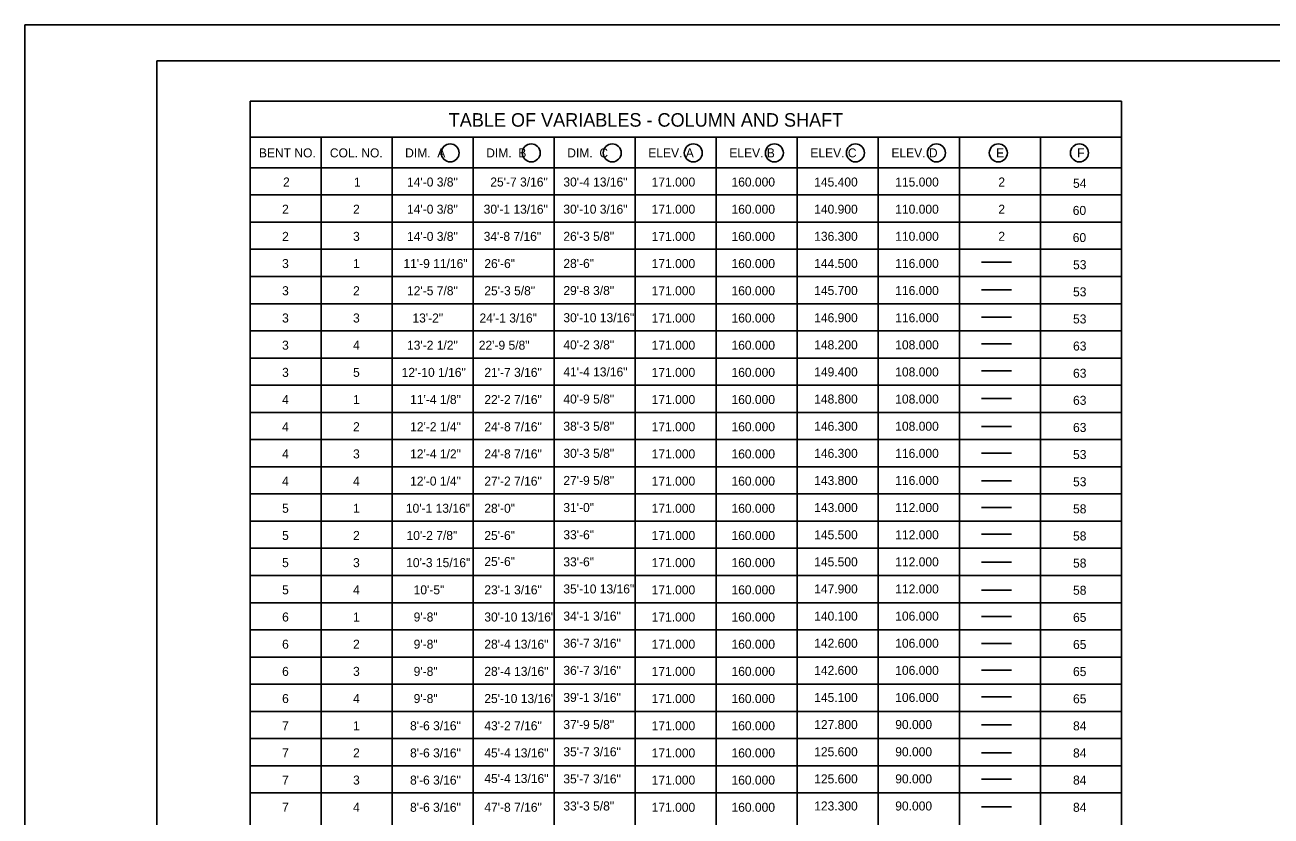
# Model space of a CAD drawing. Extents: x -133.1 to -97, y -1.7 to 20.3.
# Drawn here: x -133.14 to -115.84, y 9.34 to 20.31 of the extents above; entities that cross this region are included whole.
import ezdxf

# ---------------------------------------------------------------- set-up
doc = ezdxf.new("R2010")
doc.units = 0
for name, color, linetype in [('BR_AUTO DIMENSION', 7, 'Continuous'), ('BR_BORDER LINES', 7, 'Continuous'), ('BR_TABLE LINES', 7, 'Continuous'), ('BR_TEXT', 7, 'Continuous'), ('Level 31', 7, 'Continuous')]:
    doc.layers.add(name, color=color, linetype=linetype)

msp = doc.modelspace()

# ---------------------------------------------------------------- linework, layer by layer
at = {"layer": 'BR_AUTO DIMENSION'}
for p, q in [((-120.17, -0.146), (-120.17, 18.753)), ((-119.045, -0.146), (-119.045, 18.753))]:
    msp.add_line(p, q, dxfattribs=at)
at = {"layer": 'BR_BORDER LINES'}
for p in [(-97.642, 19.809), (-131.308, -1.191)]:
    msp.add_line(p, (-131.308, 19.809), dxfattribs=at)
at = {"layer": 'BR_TABLE LINES'}
for p, q in [((-130.014, 19.253), (-117.92, 19.253)), ((-130.014, -0.146), (-130.014, 19.253)), ((-117.92, -0.146), (-117.92, 19.253)), ((-130.014, 18.753), (-117.92, 18.753)), ((-129.03, -0.146), (-129.029, 18.753)), ((-128.045, -0.146), (-128.045, 18.753)), ((-126.92, -0.146), (-126.92, 18.753)), ((-125.795, -0.146), (-125.795, 18.753)), ((-124.67, -0.146), (-124.67, 18.753)), ((-123.545, -0.146), (-123.545, 18.753)), ((-122.42, -0.146), (-122.42, 18.753)), ((-121.295, -0.146), (-121.295, 18.753)), ((-120.17, -0.146), (-120.17, 18.753)), ((-119.045, -0.146), (-119.045, 18.753)), ((-130.014, 18.329), (-117.92, 18.329)), ((-130.014, 17.951), (-117.92, 17.951)), ((-130.014, 17.574), (-117.92, 17.574)), ((-130.014, 17.197), (-117.92, 17.197)), ((-130.014, 16.82), (-117.92, 16.82)), ((-130.014, 16.443), (-117.92, 16.443)), ((-130.014, 16.066), (-117.92, 16.066)), ((-130.014, 15.689), (-117.92, 15.689)), ((-130.014, 15.312), (-117.92, 15.312)), ((-130.014, 14.935), (-117.92, 14.935)), ((-130.014, 14.558), (-117.92, 14.558)), ((-130.014, 14.181), (-117.92, 14.181)), ((-130.014, 13.804), (-117.92, 13.804)), ((-130.014, 13.427), (-117.92, 13.427)), ((-130.014, 13.05), (-117.92, 13.05)), ((-130.014, 12.673), (-117.92, 12.673)), ((-130.014, 12.296), (-117.92, 12.296)), ((-130.014, 11.919), (-117.92, 11.919)), ((-130.014, 11.542), (-117.92, 11.542)), ((-130.014, 11.165), (-117.92, 11.165)), ((-130.014, 10.788), (-117.92, 10.788)), ((-130.014, 10.411), (-117.92, 10.411)), ((-130.014, 10.034), (-117.92, 10.034)), ((-130.014, 9.657), (-117.92, 9.657))]:
    msp.add_line(p, q, dxfattribs=at)
at = {"layer": 'BR_TEXT'}
for p, q in [((-119.863, 17.02), (-119.445, 17.02)), ((-119.863, 16.633), (-119.445, 16.633)), ((-119.863, 16.254), (-119.445, 16.254)), ((-119.863, 15.884), (-119.445, 15.884)), ((-119.863, 15.514), (-119.445, 15.514)), ((-119.863, 15.126), (-119.445, 15.126)), ((-119.863, 14.738), (-119.445, 14.738)), ((-119.863, 14.37), (-119.445, 14.37)), ((-119.863, 13.986), (-119.445, 13.986)), ((-119.863, 13.616), (-119.445, 13.616)), ((-119.863, 13.246), (-119.445, 13.246)), ((-119.863, 12.858), (-119.445, 12.858)), ((-119.863, 12.47), (-119.445, 12.47)), ((-119.863, 12.103), (-119.445, 12.103)), ((-119.863, 11.731), (-119.445, 11.731)), ((-119.863, 11.361), (-119.445, 11.361)), ((-119.863, 10.991), (-119.445, 10.991)), ((-119.863, 10.603), (-119.445, 10.603)), ((-119.863, 10.215), (-119.445, 10.215)), ((-119.863, 9.847), (-119.445, 9.847)), ((-119.863, 9.467), (-119.445, 9.467))]:
    msp.add_line(p, q, dxfattribs=at)
for centre in [(-127.238, 18.535), (-126.113, 18.535), (-124.988, 18.535), (-123.863, 18.535), (-122.738, 18.535), (-121.613, 18.535), (-120.488, 18.535), (-119.629, 18.535), (-119.629, 18.535), (-118.504, 18.535)]:
    msp.add_circle(centre, 0.125, dxfattribs=at)
at = {"layer": 'Level 31'}
msp.add_lwpolyline([(-133.141, -1.691), (-97.141, -1.691), (-97.141, 20.309), (-133.141, 20.309)], close=True, dxfattribs=at)

# ---------------------------------------------------------------- texts
at = {"layer": 'BR_TEXT'}
msp.add_text('TABLE OF VARIABLES - COLUMN AND SHAFT', height=0.1875, dxfattribs=at).set_placement((-127.258, 18.898))
for s, p in [('BENT NO.', (-129.893, 18.472)), ('COL. NO.', (-128.908, 18.472)), ('DIM.  A', (-127.863, 18.472)), ('DIM.  B', (-126.738, 18.472)), ('DIM.  C', (-125.613, 18.472)), ('ELEV. A', (-124.488, 18.472)), ('ELEV. B', (-123.363, 18.472)), ('ELEV. C', (-122.238, 18.472)), ('ELEV. D', (-121.113, 18.472)), ('F', (-119.66, 18.472)), ('E', (-119.66, 18.472)), ('F', (-118.535, 18.472)), ('2', (-129.558, 18.068)), ('1', (-128.573, 18.068)), ('14\'-0 3/8"', (-127.837, 18.068)), ('25\'-7 3/16"', (-126.681, 18.068)), ('30\'-4 13/16"', (-125.667, 18.068)), ('171.000', (-124.441, 18.068)), ('160.000', (-123.333, 18.068)), ('145.400', (-122.185, 18.068)), ('115.000', (-121.06, 18.068)), ('2', (-119.629, 18.068)), ('54', (-118.592, 18.05)), ('2', (-129.571, 17.691)), ('2', (-128.586, 17.691)), ('14\'-0 3/8"', (-127.837, 17.691)), ('30\'-1 13/16"', (-126.773, 17.691)), ('30\'-10 3/16"', (-125.667, 17.691)), ('171.000', (-124.441, 17.691)), ('160.000', (-123.333, 17.691)), ('140.900', (-122.185, 17.691)), ('110.000', (-121.06, 17.691)), ('2', (-119.629, 17.691)), ('60', (-118.596, 17.674)), ('2', (-129.571, 17.314)), ('3', (-128.586, 17.314)), ('14\'-0 3/8"', (-127.837, 17.314)), ('34\'-8 7/16"', (-126.773, 17.314)), ('26\'-3 5/8"', (-125.667, 17.315)), ('171.000', (-124.441, 17.314)), ('160.000', (-123.333, 17.314)), ('136.300', (-122.185, 17.315)), ('110.000', (-121.06, 17.315)), ('2', (-119.629, 17.315)), ('60', (-118.596, 17.298)), ('3', (-129.571, 16.937)), ('1', (-128.586, 16.937)), ('11\'-9 11/16"', (-127.887, 16.937)), ('26\'-6"', (-126.764, 16.937)), ('28\'-6"', (-125.667, 16.939)), ('171.000', (-124.441, 16.937)), ('160.000', (-123.333, 16.937)), ('144.500', (-122.185, 16.939)), ('116.000', (-121.06, 16.939)), ('53', (-118.592, 16.921)), ('3', (-129.571, 16.56)), ('2', (-128.586, 16.56)), ('12\'-5 7/8"', (-127.837, 16.56)), ('25\'-3 5/8"', (-126.764, 16.56)), ('29\'-8 3/8"', (-125.667, 16.563)), ('171.000', (-124.441, 16.56)), ('160.000', (-123.333, 16.56)), ('145.700', (-122.185, 16.563)), ('116.000', (-121.06, 16.563)), ('53', (-118.592, 16.545)), ('3', (-129.571, 16.182)), ('3', (-128.586, 16.182)), ('13\'-2"', (-127.762, 16.182)), ('24\'-1 3/16"', (-126.831, 16.182)), ('30\'-10 13/16"', (-125.667, 16.186)), ('171.000', (-124.441, 16.182)), ('160.000', (-123.333, 16.182)), ('146.900', (-122.185, 16.186)), ('116.000', (-121.06, 16.186)), ('53', (-118.592, 16.169)), ('3', (-129.571, 15.805)), ('4', (-128.586, 15.805)), ('13\'-2 1/2"', (-127.837, 15.805)), ('22\'-9 5/8"', (-126.841, 15.805)), ('40\'-2 3/8"', (-125.667, 15.81)), ('171.000', (-124.441, 15.805)), ('160.000', (-123.333, 15.805)), ('148.200', (-122.185, 15.81)), ('108.000', (-121.06, 15.81)), ('63', (-118.592, 15.793)), ('3', (-129.571, 15.428)), ('5', (-128.586, 15.428)), ('12\'-10 1/16"', (-127.912, 15.428)), ('21\'-7 3/16"', (-126.764, 15.428)), ('41\'-4 13/16"', (-125.667, 15.434)), ('171.000', (-124.441, 15.428)), ('160.000', (-123.333, 15.428)), ('149.400', (-122.185, 15.434)), ('108.000', (-121.06, 15.434)), ('63', (-118.592, 15.416)), ('4', (-129.571, 15.051)), ('1', (-128.586, 15.051)), ('11\'-4 1/8"', (-127.794, 15.051)), ('22\'-2 7/16"', (-126.764, 15.051)), ('40\'-9 5/8"', (-125.667, 15.058)), ('171.000', (-124.441, 15.051)), ('160.000', (-123.333, 15.051)), ('148.800', (-122.185, 15.058)), ('108.000', (-121.06, 15.058)), ('63', (-118.592, 15.04)), ('4', (-129.571, 14.674)), ('2', (-128.586, 14.674)), ('12\'-2 1/4"', (-127.794, 14.674)), ('24\'-8 7/16"', (-126.764, 14.674)), ('38\'-3 5/8"', (-125.667, 14.681)), ('171.000', (-124.441, 14.674)), ('160.000', (-123.333, 14.674)), ('146.300', (-122.185, 14.681)), ('108.000', (-121.06, 14.681)), ('63', (-118.592, 14.664)), ('4', (-129.571, 14.297)), ('3', (-128.586, 14.297)), ('12\'-4 1/2"', (-127.794, 14.297)), ('24\'-8 7/16"', (-126.764, 14.297)), ('30\'-3 5/8"', (-125.667, 14.305)), ('171.000', (-124.441, 14.297)), ('160.000', (-123.333, 14.297)), ('146.300', (-122.185, 14.305)), ('116.000', (-121.06, 14.305)), ('53', (-118.592, 14.288)), ('4', (-129.571, 13.92)), ('4', (-128.586, 13.92)), ('12\'-0 1/4"', (-127.794, 13.92)), ('27\'-2 7/16"', (-126.764, 13.92)), ('27\'-9 5/8"', (-125.667, 13.929)), ('171.000', (-124.441, 13.92)), ('160.000', (-123.333, 13.92)), ('143.800', (-122.185, 13.929)), ('116.000', (-121.06, 13.929)), ('53', (-118.592, 13.911)), ('5', (-129.571, 13.543)), ('1', (-128.586, 13.543)), ('10\'-1 13/16"', (-127.853, 13.543)), ('28\'-0"', (-126.764, 13.543)), ('31\'-0"', (-125.667, 13.553)), ('171.000', (-124.441, 13.543)), ('160.000', (-123.333, 13.543)), ('143.000', (-122.185, 13.553)), ('112.000', (-121.06, 13.553)), ('58', (-118.592, 13.535)), ('5', (-129.571, 13.166)), ('2', (-128.586, 13.166)), ('10\'-2 7/8"', (-127.844, 13.166)), ('25\'-6"', (-126.764, 13.166)), ('33\'-6"', (-125.667, 13.176)), ('171.000', (-124.441, 13.166)), ('160.000', (-123.333, 13.166)), ('145.500', (-122.185, 13.176)), ('112.000', (-121.06, 13.176)), ('58', (-118.592, 13.159)), ('5', (-129.571, 12.789)), ('3', (-128.586, 12.789)), ('10\'-3 15/16"', (-127.849, 12.789)), ('25\'-6"', (-126.764, 12.805)), ('33\'-6"', (-125.667, 12.8)), ('171.000', (-124.441, 12.789)), ('160.000', (-123.333, 12.789)), ('145.500', (-122.185, 12.8)), ('112.000', (-121.06, 12.8)), ('58', (-118.592, 12.783)), ('5', (-129.571, 12.412)), ('4', (-128.586, 12.412)), ('10\'-5"', (-127.745, 12.412)), ('23\'-1 3/16"', (-126.764, 12.412)), ('35\'-10 13/16"', (-125.667, 12.424)), ('171.000', (-124.441, 12.412)), ('160.000', (-123.333, 12.412)), ('147.900', (-122.185, 12.424)), ('112.000', (-121.06, 12.424)), ('58', (-118.592, 12.406)), ('6', (-129.571, 12.035)), ('1', (-128.586, 12.035)), ('9\'-8"', (-127.745, 12.035)), ('30\'-10 13/16"', (-126.764, 12.035)), ('34\'-1 3/16"', (-125.667, 12.048)), ('171.000', (-124.441, 12.035)), ('160.000', (-123.333, 12.035)), ('140.100', (-122.185, 12.048)), ('106.000', (-121.06, 12.048)), ('65', (-118.592, 12.03)), ('6', (-129.571, 11.658)), ('2', (-128.586, 11.658)), ('9\'-8"', (-127.745, 11.658)), ('28\'-4 13/16"', (-126.764, 11.658)), ('36\'-7 3/16"', (-125.667, 11.671)), ('171.000', (-124.441, 11.658)), ('160.000', (-123.333, 11.658)), ('142.600', (-122.185, 11.671)), ('106.000', (-121.06, 11.671)), ('65', (-118.592, 11.654)), ('36\'-7 3/16"', (-125.667, 11.295)), ('142.600', (-122.185, 11.295)), ('106.000', (-121.06, 11.295)), ('6', (-129.571, 11.281)), ('3', (-128.586, 11.281)), ('9\'-8"', (-127.745, 11.281)), ('28\'-4 13/16"', (-126.764, 11.281)), ('171.000', (-124.441, 11.281)), ('160.000', (-123.333, 11.281)), ('65', (-118.592, 11.278)), ('6', (-129.571, 10.904)), ('4', (-128.586, 10.904)), ('9\'-8"', (-127.745, 10.904)), ('25\'-10 13/16"', (-126.764, 10.904)), ('39\'-1 3/16"', (-125.667, 10.919)), ('171.000', (-124.441, 10.904)), ('160.000', (-123.333, 10.904)), ('145.100', (-122.185, 10.919)), ('106.000', (-121.06, 10.919)), ('65', (-118.592, 10.901)), ('7', (-129.571, 10.527)), ('1', (-128.586, 10.527)), ('8\'-6 3/16"', (-127.795, 10.527)), ('43\'-2 7/16"', (-126.764, 10.527)), ('37\'-9 5/8"', (-125.667, 10.543)), ('171.000', (-124.441, 10.527)), ('160.000', (-123.333, 10.527)), ('127.800', (-122.185, 10.543)), ('90.000', (-121.06, 10.543)), ('84', (-118.592, 10.525)), ('7', (-129.571, 10.15)), ('2', (-128.586, 10.15)), ('8\'-6 3/16"', (-127.795, 10.15)), ('45\'-4 13/16"', (-126.764, 10.15)), ('35\'-7 3/16"', (-125.667, 10.166)), ('171.000', (-124.441, 10.15)), ('160.000', (-123.333, 10.15)), ('125.600', (-122.185, 10.166)), ('90.000', (-121.06, 10.166)), ('84', (-118.592, 10.149)), ('7', (-129.571, 9.773)), ('3', (-128.586, 9.773)), ('8\'-6 3/16"', (-127.795, 9.773)), ('45\'-4 13/16"', (-126.764, 9.795)), ('35\'-7 3/16"', (-125.667, 9.79)), ('171.000', (-124.441, 9.773)), ('160.000', (-123.333, 9.773)), ('125.600', (-122.185, 9.79)), ('90.000', (-121.06, 9.79)), ('84', (-118.592, 9.773)), ('7', (-129.571, 9.396)), ('4', (-128.586, 9.396)), ('8\'-6 3/16"', (-127.795, 9.396)), ('47\'-8 7/16"', (-126.764, 9.396)), ('33\'-3 5/8"', (-125.667, 9.414)), ('171.000', (-124.441, 9.396)), ('160.000', (-123.333, 9.396)), ('123.300', (-122.185, 9.414)), ('90.000', (-121.06, 9.414)), ('84', (-118.592, 9.396))]:
    msp.add_text(s, height=0.125, rotation=360, dxfattribs=at).set_placement(p)

doc.saveas('drawing.dxf')
